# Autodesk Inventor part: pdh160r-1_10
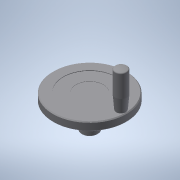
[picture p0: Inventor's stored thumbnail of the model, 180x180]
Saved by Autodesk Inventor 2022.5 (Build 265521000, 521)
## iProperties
Created: 2016-12
Part Number: pdh160r-1_10
Material: 一般
Document SubType Name: Modeling
Designer: imaocorp
Density: 1 g/cm^3
Appearance: 既定
Author: imaocorp
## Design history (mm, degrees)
node "pdh160r-1_10.x_t1"
node "pdh160r-1_10"
node "Base1"
